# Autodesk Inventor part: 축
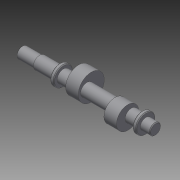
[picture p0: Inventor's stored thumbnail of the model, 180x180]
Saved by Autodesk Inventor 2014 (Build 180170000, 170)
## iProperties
Created: 2014-12
Part Number: 축
Material: 일반
Document SubType Name: Modeling
Designer: Owner
Density: 1 g/cm^3
Appearance: 기본값
Mass: 62.2111 g
Surface Area: 152.622 cm^2
Volume: 62.2111 cm^3
Author: Owner
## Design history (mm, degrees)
sketch "스케치1"
  geometry: L1 (-90, 0)-(90, 0); L2 (-90, 0)-(-90, 7.5); L3 (-90, 7.5)-(-66, 7.5); L4 (-66, 7.5)-(-66, 8.5); L5 (-66, 8.5)-(-39, 8.5); L6 (-39, 8.5)-(-39, 13); L7 (-39, 13)-(-34, 13); L8 (-34, 13)-(-34, 8.5); L9 (-34, 8.5)-(72, 8.5); L10 (72, 8.5)-(72, 13); L11 (72, 13)-(77, 13); L12 (77, 13)-(77, 7.5); L13 (77, 7.5)-(90, 7.5); L14 (90, 7.5)-(90, 0); 2 further points
  constraints: 28 end point, 10 parallel, 2 horizontal alignment, 2 perpendicular, 1 coincident, 1 collinear, 1 horizontal, 1 midpoint
  dimensions: "d0" = 180 distance of L1.start L1.end; "d1" = 15 diameter of L3 L1; "d2" = 17 diameter of L5 L1; "d3" = 26 diameter of L7 L1; "d4" = 17 diameter of L9 L1; "d5" = 15 diameter of L13 L1; "d6" = 5 distance of L10.end L11.end; "d7" = 26 diameter of L11 L1; "d8" = 5 distance between parallel lines of L8 L6; "d9" = 24 distance of L2.end L3.end; "d10" = 27 distance of L4.end L5.end; "d11" = 13 distance of L12.end L13.end
revolve "회전1" sketch "스케치1" stored, may be unused: angle "d12" = 90 deg
node "작업 평면1"
sketch "스케치2"
  geometry: C1 r 17.5 at (0, 6); 1 further point
  constraints: 1 centre point, 1 vertical alignment
  dimensions: "d14" = 35 diameter of C1; "d15" = 6 distance of C1.centre point (0, 0)
extrude "돌출1" join sketch "스케치2" distance "d16" = 17; taper "d17" = 0 deg
node "작업 평면2"
sketch "스케치3"
  geometry: C1 r 15 at (0, -5); 1 further point
  constraints: 1 centre point, 1 vertical alignment
  dimensions: "d19" = 30 diameter of C1; "d20" = 5 distance of C1.centre point (0, 0)
extrude "돌출2" join sketch "스케치3" distance "d21" = 17; taper "d22" = 0 deg
node "작업 평면3"
sketch "스케치4"
  geometry: L1 (29.5, 0)-(-5.5, 0); L2 (12, 2.5)-(-5.5, 2.5); L3 (-5.5, -2.5)-(12, -2.5); L4 (12, 7.5)-(12, -7.5) reference; L5 (-12, 7.5)-(-12, -7.5) reference; A1 r 2.5 centre (-5.5, 0) between (-5.5, 2.5) and (-5.5, -2.5); 3 further points
  constraints: 8 end point, 2 midpoint, 2 point on circle, 2 point on line, 2 tangent, 1 centre point, 1 coincident, 1 horizontal, 1 parallel
  dimensions: "d23" = 5 distance between parallel lines of L2 L3; "d24" = 20 dimension on A1 L4
extrude "돌출3" cut sketch "스케치4" distance "d25" = 3; taper "d26" = 0 deg
chamfer "모따기1" distance "d27" = 1; stored, may be unused: second distance "d28" = 2, angle "d29" = 45 deg
node "솔리드1"
node "투영된 루프1"
other parameters: "d13" = -70.5, "d18" = -32.5
